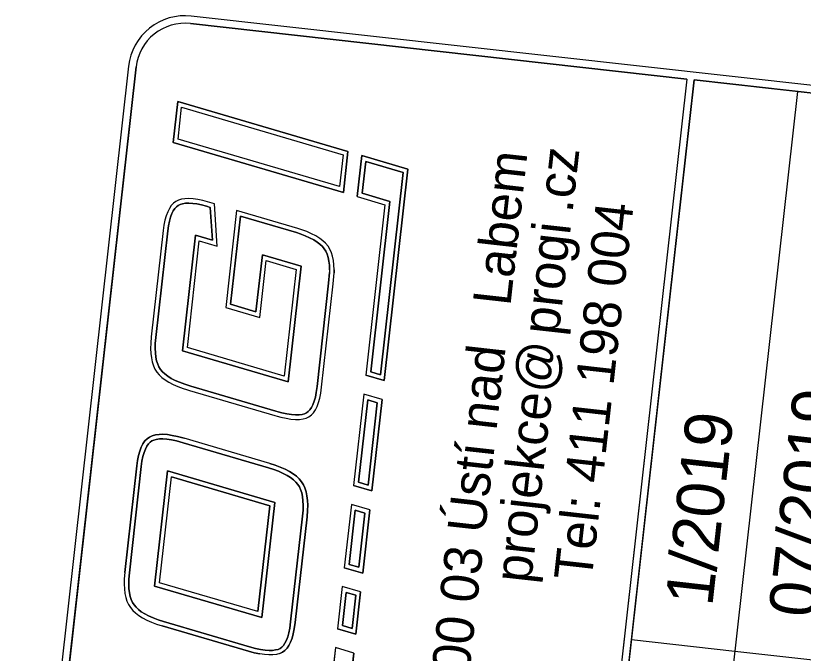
# Model space of a CAD drawing. Extents: x -734953 to -734775, y -1144697 to -1144368.
# Drawn here: x -734813.98 to -734794.21, y -1144400.21 to -1144384.19 of the extents above; entities that cross this region are included whole.
import ezdxf

# ---------------------------------------------------------------- set-up
doc = ezdxf.new("R2010")
doc.units = 0
doc.layers.add('000_rozpiska', color=7, linetype='Continuous')

# ---------------------------------------------------------------- blocks, each defined once
blk = doc.blocks.new('A$C2B726605')
at = {"layer": '000_rozpiska'}
for p, q in [((-8.894, 71.716), (-181.794, 71.716)), ((-8.894, 71.716), (-181.794, 71.716)), ((-8.894, 71.336), (-63.044, 71.336)), ((-34.759, 68.816), (-34.511, 68.836)), ((-34.511, 68.836), (-34.202, 68.844)), ((-34.202, 68.844), (-28.821, 68.844)), ((-28.821, 68.844), (-28.555, 68.837)), ((-28.555, 68.837), (-28.314, 68.816)), ((-23.536, 68.882), (-23.718, 68.8)), ((-23.336, 68.949), (-23.536, 68.882)), ((-23.113, 69), (-23.336, 68.949)), ((-22.876, 69.037), (-23.113, 69)), ((-22.611, 69.06), (-22.876, 69.037)), ((-22.599, 68.832), (-22.849, 68.811)), ((-22.293, 69.067), (-22.611, 69.06)), ((-22.29, 68.839), (-22.599, 68.832)), ((-16.9, 69.067), (-22.293, 69.067)), ((-16.903, 68.839), (-22.29, 68.839)), ((-16.644, 68.832), (-16.903, 68.839)), ((-16.631, 69.06), (-16.9, 69.067)), ((-16.41, 68.812), (-16.644, 68.832)), ((-16.382, 69.039), (-16.631, 69.06)), ((-16.158, 69.003), (-16.382, 69.039)), ((-15.946, 68.95), (-16.158, 69.003)), ((-15.774, 68.885), (-15.946, 68.95)), ((-15.623, 68.805), (-15.774, 68.885)), ((-14.003, 60.287), (-12.456, 69.067)), ((-13.731, 60.515), (-12.264, 68.839)), ((-12.456, 69.067), (-10.382, 69.067)), ((-12.264, 68.839), (-10.654, 68.839)), ((-10.654, 68.839), (-12.121, 60.515)), ((-10.382, 69.067), (-11.929, 60.287)), ((-6.424, 43.784), (-6.424, 68.866)), ((-6.044, 8.894), (-6.044, 68.866)), ((-6.044, 8.894), (-6.044, 68.866)), ((-35.877, 68.32), (-35.774, 68.43)), ((-35.774, 68.43), (-35.655, 68.523)), ((-35.655, 68.523), (-35.523, 68.603)), ((-35.523, 68.603), (-35.366, 68.674)), ((-35.366, 68.674), (-35.185, 68.734)), ((-35.185, 68.734), (-34.983, 68.781)), ((-34.983, 68.781), (-34.759, 68.816)), ((-28.314, 68.816), (-28.102, 68.782)), ((-28.102, 68.782), (-27.922, 68.735)), ((-27.922, 68.735), (-27.774, 68.68)), ((-27.774, 68.68), (-27.647, 68.612)), ((-27.647, 68.612), (-27.556, 68.541)), ((-27.556, 68.541), (-27.482, 68.458)), ((-27.482, 68.458), (-27.424, 68.363)), ((-24.14, 68.463), (-24.252, 68.312)), ((-24.014, 68.594), (-24.14, 68.463)), ((-23.875, 68.705), (-24.014, 68.594)), ((-23.718, 68.8), (-23.875, 68.705)), ((-23.744, 68.517), (-23.86, 68.425)), ((-23.612, 68.597), (-23.744, 68.517)), ((-23.453, 68.67), (-23.612, 68.597)), ((-23.274, 68.729), (-23.453, 68.67)), ((-23.07, 68.776), (-23.274, 68.729)), ((-22.849, 68.811), (-23.07, 68.776)), ((-16.203, 68.779), (-16.41, 68.812)), ((-16.014, 68.732), (-16.203, 68.779)), ((-15.868, 68.677), (-16.014, 68.732)), ((-15.744, 68.612), (-15.868, 68.677)), ((-15.646, 68.54), (-15.744, 68.612)), ((-15.57, 68.458), (-15.646, 68.54)), ((-15.494, 68.711), (-15.623, 68.805)), ((-15.513, 68.368), (-15.57, 68.458)), ((-15.389, 68.598), (-15.494, 68.711)), ((-15.31, 68.474), (-15.389, 68.598)), ((-15.247, 68.325), (-15.31, 68.474)), ((-36.072, 68.03), (-35.977, 68.188)), ((-35.977, 68.188), (-35.877, 68.32)), ((-27.424, 68.363), (-27.377, 68.245)), ((-27.377, 68.245), (-27.339, 68.093)), ((-27.339, 68.093), (-27.316, 67.921)), ((-24.358, 68.136), (-24.456, 67.934)), ((-24.252, 68.312), (-24.358, 68.136)), ((-24.062, 68.185), (-24.157, 68.028)), ((-23.966, 68.315), (-24.062, 68.185)), ((-23.86, 68.425), (-23.966, 68.315)), ((-15.462, 68.25), (-15.513, 68.368)), ((-15.425, 68.113), (-15.462, 68.25)), ((-15.401, 67.946), (-15.425, 68.113)), ((-15.201, 68.16), (-15.247, 68.325)), ((-15.174, 67.968), (-15.201, 68.16)), ((-36.313, 67.406), (-36.24, 67.64)), ((-36.24, 67.64), (-36.158, 67.849)), ((-36.158, 67.849), (-36.072, 68.03)), ((-27.309, 67.715), (-27.318, 67.49)), ((-27.316, 67.921), (-27.309, 67.715)), ((-24.542, 67.709), (-24.617, 67.47)), ((-24.456, 67.934), (-24.542, 67.709)), ((-24.247, 67.843), (-24.327, 67.634)), ((-24.157, 68.028), (-24.247, 67.843)), ((-15.39, 67.746), (-15.401, 67.946)), ((-15.396, 67.53), (-15.39, 67.746)), ((-15.161, 67.749), (-15.174, 67.968)), ((-15.168, 67.516), (-15.161, 67.749)), ((-36.377, 67.15), (-36.313, 67.406)), ((-35.686, 61.98), (-34.711, 67.51)), ((-35.414, 62.208), (-34.52, 67.282)), ((-34.711, 67.51), (-28.895, 67.51)), ((-34.52, 67.282), (-29.166, 67.282)), ((-30.06, 62.208), (-29.166, 67.282)), ((-29.869, 61.98), (-28.895, 67.51)), ((-27.318, 67.49), (-27.343, 67.228)), ((-24.617, 67.47), (-24.689, 67.189)), ((-24.398, 67.408), (-24.466, 67.138)), ((-24.327, 67.634), (-24.398, 67.408)), ((-23.773, 61.981), (-22.812, 67.436)), ((-22.812, 67.436), (-16.956, 67.436)), ((-16.956, 67.436), (-17.109, 66.562)), ((-15.455, 67.047), (-15.418, 67.292)), ((-15.418, 67.292), (-15.396, 67.53)), ((-15.23, 67.01), (-15.192, 67.265)), ((-15.192, 67.265), (-15.168, 67.516)), ((-37.443, 62.463), (-36.658, 66.917)), ((-37.218, 62.426), (-36.434, 66.871)), ((-36.434, 66.871), (-36.377, 67.15)), ((-27.394, 66.891), (-28.17, 62.485)), ((-27.946, 62.446), (-27.168, 66.857)), ((-27.343, 67.228), (-27.394, 66.891)), ((-24.755, 66.868), (-25.53, 62.465)), ((-24.723, 67.024), (-24.755, 66.868)), ((-24.689, 67.189), (-24.723, 67.024)), ((-24.499, 66.978), (-24.531, 66.825)), ((-24.466, 67.138), (-24.499, 66.978)), ((-23.501, 62.209), (-22.62, 67.208)), ((-22.62, 67.208), (-17.227, 67.208)), ((-17.227, 67.208), (-17.39, 66.281)), ((-17.109, 66.562), (-15.489, 66.851)), ((-15.489, 66.851), (-15.455, 67.047)), ((-15.293, 66.654), (-15.23, 67.01)), ((-24.531, 66.825), (-25.305, 62.43)), ((-17.39, 66.281), (-15.293, 66.654)), ((-20.41, 65.519), (-20.721, 63.755)), ((-20.219, 65.291), (-20.45, 63.983)), ((-15.492, 65.519), (-20.41, 65.519)), ((-15.764, 65.291), (-20.219, 65.291)), ((-16.272, 62.408), (-15.764, 65.291)), ((-16.049, 62.363), (-15.492, 65.519)), ((-20.721, 63.755), (-17.836, 63.755)), ((-20.45, 63.983), (-17.564, 63.983)), ((-17.836, 63.755), (-18.108, 62.209)), ((-17.564, 63.983), (-17.916, 61.981)), ((-37.288, 61.87), (-37.262, 62.134)), ((-37.262, 62.134), (-37.218, 62.426)), ((-35.414, 62.208), (-30.06, 62.208)), ((-28.229, 62.211), (-28.289, 61.967)), ((-28.168, 62.494), (-28.229, 62.211)), ((-25.574, 62.154), (-25.602, 61.884)), ((-25.547, 62.345), (-25.574, 62.154)), ((-25.53, 62.465), (-25.547, 62.345)), ((-25.348, 62.126), (-25.375, 61.868)), ((-25.321, 62.313), (-25.348, 62.126)), ((-25.305, 62.43), (-25.321, 62.313)), ((-18.108, 62.209), (-23.501, 62.209)), ((-16.383, 61.95), (-16.316, 62.214)), ((-16.316, 62.214), (-16.272, 62.408)), ((-16.163, 61.888), (-16.095, 62.161)), ((-16.095, 62.161), (-16.049, 62.363)), ((-37.298, 61.64), (-37.288, 61.87)), ((-35.686, 61.98), (-29.869, 61.98)), ((-28.367, 61.72), (-28.448, 61.51)), ((-28.289, 61.967), (-28.367, 61.72)), ((-25.602, 61.884), (-25.612, 61.64)), ((-25.375, 61.868), (-25.384, 61.64)), ((-17.916, 61.981), (-23.773, 61.981)), ((-16.537, 61.505), (-16.456, 61.717)), ((-16.456, 61.717), (-16.383, 61.95)), ((-16.241, 61.642), (-16.163, 61.888)), ((-37.291, 61.435), (-37.298, 61.64)), ((-37.268, 61.258), (-37.291, 61.435)), ((-28.537, 61.326), (-28.63, 61.17)), ((-28.448, 61.51), (-28.537, 61.326)), ((-25.612, 61.64), (-25.605, 61.413)), ((-25.605, 61.413), (-25.579, 61.21)), ((-25.384, 61.64), (-25.377, 61.431)), ((-25.377, 61.431), (-25.354, 61.252)), ((-16.719, 61.167), (-16.626, 61.321)), ((-16.626, 61.321), (-16.537, 61.505)), ((-16.426, 61.212), (-16.328, 61.415)), ((-16.328, 61.415), (-16.241, 61.642)), ((-37.231, 61.111), (-37.268, 61.258)), ((-37.184, 60.99), (-37.231, 61.111)), ((-37.126, 60.896), (-37.184, 60.99)), ((-28.835, 60.928), (-28.949, 60.838)), ((-28.729, 61.038), (-28.835, 60.928)), ((-28.63, 61.17), (-28.729, 61.038)), ((-25.579, 61.21), (-25.534, 61.032)), ((-25.534, 61.032), (-25.477, 60.887)), ((-25.354, 61.252), (-25.317, 61.102)), ((-25.317, 61.102), (-25.272, 60.989)), ((-25.272, 60.989), (-25.213, 60.893)), ((-17.039, 60.833), (-16.924, 60.924)), ((-16.924, 60.924), (-16.816, 61.036)), ((-16.816, 61.036), (-16.719, 61.167)), ((-16.642, 60.889), (-16.53, 61.04)), ((-16.53, 61.04), (-16.426, 61.212)), ((-37.055, 60.819), (-37.126, 60.896)), ((-36.959, 60.747), (-37.055, 60.819)), ((-36.839, 60.683), (-36.959, 60.747)), ((-36.687, 60.627), (-36.839, 60.683)), ((-36.506, 60.581), (-36.687, 60.627)), ((-36.295, 60.547), (-36.506, 60.581)), ((-36.059, 60.526), (-36.295, 60.547)), ((-35.746, 60.519), (-36.059, 60.526)), ((-30.401, 60.519), (-35.746, 60.519)), ((-30.095, 60.527), (-30.401, 60.519)), ((-29.849, 60.547), (-30.095, 60.527)), ((-29.624, 60.582), (-29.849, 60.547)), ((-29.421, 60.629), (-29.624, 60.582)), ((-29.242, 60.688), (-29.421, 60.629)), ((-29.082, 60.76), (-29.242, 60.688)), ((-28.949, 60.838), (-29.082, 60.76)), ((-25.477, 60.887), (-25.396, 60.755)), ((-25.396, 60.755), (-25.295, 60.643)), ((-25.295, 60.643), (-25.168, 60.55)), ((-25.213, 60.893), (-25.141, 60.813)), ((-25.168, 60.55), (-25.016, 60.469)), ((-25.141, 60.813), (-25.047, 60.744)), ((-25.047, 60.744), (-24.922, 60.677)), ((-24.922, 60.677), (-24.774, 60.621)), ((-24.774, 60.621), (-24.592, 60.576)), ((-24.592, 60.576), (-24.381, 60.543)), ((-24.381, 60.543), (-24.143, 60.522)), ((-24.143, 60.522), (-23.837, 60.515)), ((-18.622, 60.515), (-18.073, 60.532)), ((-17.938, 60.543), (-18.073, 60.532)), ((-17.938, 60.543), (-17.714, 60.577)), ((-17.714, 60.577), (-17.514, 60.623)), ((-17.514, 60.623), (-17.334, 60.683)), ((-17.334, 60.683), (-17.18, 60.751)), ((-17.252, 60.47), (-17.076, 60.547)), ((-17.18, 60.751), (-17.039, 60.833)), ((-17.076, 60.547), (-16.91, 60.645)), ((-16.91, 60.645), (-16.771, 60.755)), ((-16.771, 60.755), (-16.642, 60.889)), ((-25.016, 60.469), (-24.842, 60.403)), ((-24.842, 60.403), (-24.638, 60.353)), ((-24.638, 60.353), (-24.409, 60.316)), ((-24.409, 60.316), (-24.156, 60.295)), ((-24.156, 60.295), (-23.84, 60.287)), ((-23.84, 60.287), (-18.618, 60.287)), ((-23.837, 60.515), (-18.622, 60.515)), ((-18.618, 60.287), (-18.06, 60.305)), ((-17.912, 60.316), (-18.06, 60.305)), ((-17.912, 60.316), (-17.671, 60.353)), ((-17.671, 60.353), (-17.453, 60.403)), ((-17.453, 60.403), (-17.252, 60.47)), ((-11.929, 60.287), (-14.003, 60.287)), ((-12.121, 60.515), (-13.731, 60.515)), ((-14.128, 59.574), (-14.38, 58.143)), ((-13.937, 59.346), (-14.189, 57.915)), ((-14.128, 59.574), (-12.055, 59.574)), ((-13.937, 59.346), (-12.326, 59.346)), ((-12.326, 59.346), (-12.666, 57.421)), ((-12.055, 59.574), (-12.474, 57.193)), ((-36.779, 58.143), (-38.204, 58.143)), ((-36.946, 57.193), (-36.779, 58.143)), ((-35.996, 57.193), (-35.829, 58.143)), ((-33.691, 58.143), (-35.829, 58.143)), ((-35.724, 57.421), (-35.637, 57.915)), ((-33.963, 57.915), (-35.637, 57.915)), ((-34.05, 57.421), (-33.963, 57.915)), ((-33.859, 57.193), (-33.691, 58.143)), ((-32.909, 57.193), (-32.741, 58.143)), ((-29.535, 58.143), (-32.741, 58.143)), ((-32.637, 57.421), (-32.55, 57.915)), ((-29.807, 57.915), (-32.55, 57.915)), ((-29.894, 57.421), (-29.807, 57.915)), ((-29.702, 57.193), (-29.535, 58.143)), ((-28.752, 57.193), (-28.585, 58.143)), ((-23.954, 58.143), (-28.585, 58.143)), ((-28.481, 57.421), (-28.393, 57.915)), ((-24.225, 57.915), (-28.393, 57.915)), ((-24.312, 57.421), (-24.225, 57.915)), ((-24.121, 57.193), (-23.954, 58.143)), ((-23.171, 57.193), (-23.004, 58.143)), ((-14.38, 58.143), (-23.004, 58.143)), ((-22.899, 57.421), (-22.812, 57.915)), ((-14.189, 57.915), (-22.812, 57.915)), ((-34.05, 57.421), (-35.724, 57.421)), ((-29.894, 57.421), (-32.637, 57.421)), ((-24.312, 57.421), (-28.481, 57.421)), ((-12.666, 57.421), (-22.899, 57.421)), ((-36.946, 57.193), (-38.371, 57.193)), ((-33.859, 57.193), (-35.996, 57.193)), ((-29.702, 57.193), (-32.909, 57.193)), ((-24.121, 57.193), (-28.752, 57.193)), ((-12.474, 57.193), (-23.171, 57.193)), ((-6.424, 43.784), (-63.044, 43.784)), ((-6.424, 43.404), (-63.044, 43.404)), ((-34.734, 38.179), (-34.734, 43.404)), ((-6.424, 22.504), (-6.424, 43.404)), ((-6.424, 38.179), (-63.044, 38.179)), ((-34.734, 32.954), (-34.734, 38.179))]:
    blk.add_line(p, q, dxfattribs=at)
for points in [[(-63.044, 43.784), (-63.044, 71.336), (-8.894, 71.336)], [(-6.424, 68.866), (-6.424, 43.784), (-63.044, 43.784)], [(-28.055, 69.005), (-28.286, 69.042), (-28.542, 69.065), (-28.815, 69.072), (-34.205, 69.072), (-34.524, 69.064), (-34.786, 69.043), (-35.027, 69.005), (-35.246, 68.954), (-35.449, 68.887), (-35.629, 68.805), (-35.786, 68.711), (-35.928, 68.598), (-36.052, 68.467), (-36.166, 68.316), (-36.273, 68.138), (-36.368, 67.94), (-36.455, 67.716), (-36.532, 67.468), (-36.599, 67.2), (-36.658, 66.917), (-37.443, 62.463), (-37.489, 62.162), (-37.516, 61.886)], [(-37.388, 60.887), (-37.309, 60.758), (-37.209, 60.649), (-37.082, 60.554), (-36.933, 60.474), (-36.755, 60.409), (-36.552, 60.357), (-36.323, 60.321), (-36.071, 60.299), (-35.752, 60.291), (-30.398, 60.291), (-30.083, 60.299), (-29.822, 60.321), (-29.581, 60.358), (-29.359, 60.41), (-29.16, 60.475), (-28.977, 60.557), (-28.82, 60.65), (-28.682, 60.759), (-28.555, 60.89), (-28.441, 61.042), (-28.336, 61.217), (-28.238, 61.419), (-28.152, 61.644), (-28.07, 61.905), (-28.007, 62.16), (-27.946, 62.446), (-27.168, 66.857), (-27.117, 67.2), (-27.09, 67.475), (-27.081, 67.715), (-27.089, 67.94), (-27.115, 68.135), (-27.159, 68.315), (-27.219, 68.465), (-27.298, 68.595), (-27.4, 68.709), (-27.523, 68.804), (-27.68, 68.888), (-27.853, 68.953), (-28.055, 69.005)], [(-27.309, 67.715), (-27.316, 67.921), (-27.339, 68.093), (-27.377, 68.245), (-27.424, 68.363), (-27.482, 68.458), (-27.556, 68.541), (-27.647, 68.612), (-27.774, 68.68), (-27.922, 68.735), (-28.102, 68.782), (-28.314, 68.816), (-28.555, 68.837), (-28.821, 68.844), (-34.202, 68.844), (-34.511, 68.836), (-34.759, 68.816), (-34.983, 68.781), (-35.185, 68.734), (-35.366, 68.674), (-35.523, 68.603), (-35.655, 68.523), (-35.774, 68.43), (-35.877, 68.32), (-35.977, 68.188), (-36.072, 68.03), (-36.158, 67.849), (-36.24, 67.64), (-36.313, 67.406), (-36.377, 67.15), (-36.434, 66.871), (-37.218, 62.426), (-37.262, 62.134), (-37.288, 61.87), (-37.298, 61.64), (-37.291, 61.435), (-37.268, 61.258), (-37.231, 61.111), (-37.184, 60.99), (-37.126, 60.896), (-37.055, 60.819), (-36.959, 60.747), (-36.839, 60.683), (-36.687, 60.627), (-36.506, 60.581), (-36.295, 60.547), (-36.059, 60.526), (-35.746, 60.519), (-30.401, 60.519), (-30.095, 60.527), (-29.849, 60.547), (-29.624, 60.582), (-29.421, 60.629), (-29.242, 60.688), (-29.082, 60.76), (-28.949, 60.838), (-28.835, 60.928), (-28.729, 61.038), (-28.63, 61.17), (-28.537, 61.326), (-28.448, 61.51), (-28.367, 61.72), (-28.289, 61.967), (-28.229, 62.211), (-28.169, 62.489), (-27.394, 66.891), (-27.343, 67.228), (-27.318, 67.49), (-27.309, 67.715)], [(-28.821, 68.844), (-28.555, 68.837), (-28.314, 68.816), (-28.102, 68.782), (-27.922, 68.735), (-27.774, 68.68), (-27.647, 68.612), (-27.556, 68.541), (-27.482, 68.458), (-27.424, 68.363), (-27.377, 68.245), (-27.339, 68.093), (-27.316, 67.921), (-27.309, 67.715), (-27.318, 67.49), (-27.343, 67.228), (-27.394, 66.891), (-28.169, 62.489), (-28.229, 62.211), (-28.289, 61.967), (-28.367, 61.72), (-28.448, 61.51), (-28.537, 61.326), (-28.63, 61.17), (-28.729, 61.038), (-28.835, 60.928), (-28.949, 60.838), (-29.082, 60.76), (-29.242, 60.688), (-29.421, 60.629), (-29.624, 60.582), (-29.849, 60.547), (-30.095, 60.527), (-30.401, 60.519), (-35.746, 60.519), (-36.059, 60.526), (-36.295, 60.547), (-36.506, 60.581), (-36.687, 60.627), (-36.839, 60.683), (-36.959, 60.747), (-37.055, 60.819), (-37.126, 60.896), (-37.184, 60.99), (-37.231, 61.111), (-37.268, 61.258), (-37.291, 61.435), (-37.298, 61.64), (-37.288, 61.87), (-37.262, 62.134), (-37.218, 62.426), (-36.434, 66.871), (-36.377, 67.15), (-36.313, 67.406), (-36.24, 67.64), (-36.158, 67.849), (-36.072, 68.03), (-35.977, 68.188), (-35.877, 68.32), (-35.774, 68.43), (-35.655, 68.523), (-35.523, 68.603), (-35.366, 68.674), (-35.185, 68.734), (-34.983, 68.781), (-34.759, 68.816), (-34.511, 68.836), (-34.202, 68.844), (-28.821, 68.844)], [(-34.205, 69.072), (-34.524, 69.064), (-34.786, 69.043), (-35.027, 69.005), (-35.246, 68.954), (-35.449, 68.887), (-35.629, 68.805), (-35.786, 68.711), (-35.928, 68.598), (-36.052, 68.467), (-36.166, 68.316), (-36.273, 68.138), (-36.368, 67.94), (-36.455, 67.716), (-36.532, 67.468), (-36.599, 67.2), (-36.658, 66.917)], [(-34.205, 69.072), (-28.815, 69.072), (-28.542, 69.065), (-28.286, 69.042), (-28.055, 69.005), (-27.853, 68.953), (-27.68, 68.888), (-27.523, 68.804), (-27.4, 68.709), (-27.298, 68.595), (-27.219, 68.465), (-27.159, 68.315), (-27.115, 68.135), (-27.089, 67.94), (-27.081, 67.715), (-27.09, 67.475), (-27.117, 67.2), (-27.168, 66.857)], [(-15.946, 68.95), (-16.158, 69.003), (-16.382, 69.039), (-16.631, 69.06), (-16.9, 69.067), (-22.293, 69.067), (-22.611, 69.06), (-22.876, 69.037), (-23.113, 69), (-23.336, 68.949), (-23.536, 68.882), (-23.718, 68.8), (-23.875, 68.705), (-24.014, 68.594), (-24.14, 68.463), (-24.252, 68.312), (-24.358, 68.136), (-24.456, 67.934), (-24.542, 67.709), (-24.617, 67.47), (-24.689, 67.189), (-24.723, 67.024), (-24.755, 66.868), (-25.53, 62.465), (-25.547, 62.345), (-25.574, 62.154), (-25.602, 61.884), (-25.612, 61.64), (-25.605, 61.413), (-25.579, 61.21), (-25.534, 61.032), (-25.477, 60.887), (-25.396, 60.755), (-25.295, 60.643), (-25.168, 60.55), (-25.016, 60.469), (-24.842, 60.403), (-24.638, 60.353), (-24.409, 60.316), (-24.156, 60.295), (-23.84, 60.287), (-18.618, 60.287), (-18.06, 60.305), (-17.912, 60.316), (-17.671, 60.353), (-17.453, 60.403), (-17.252, 60.47), (-17.076, 60.547), (-16.91, 60.645), (-16.771, 60.755), (-16.642, 60.889), (-16.53, 61.04), (-16.426, 61.212), (-16.328, 61.415), (-16.241, 61.642), (-16.163, 61.888), (-16.095, 62.161), (-16.049, 62.363), (-15.492, 65.519), (-20.41, 65.519), (-20.721, 63.755), (-17.836, 63.755), (-18.108, 62.209), (-23.501, 62.209), (-22.62, 67.208), (-17.227, 67.208), (-17.39, 66.281), (-15.293, 66.654), (-15.23, 67.01), (-15.192, 67.265), (-15.168, 67.516), (-15.161, 67.749), (-15.174, 67.968), (-15.201, 68.16), (-15.247, 68.325), (-15.31, 68.474), (-15.389, 68.598), (-15.494, 68.711), (-15.623, 68.805), (-15.774, 68.885), (-15.946, 68.95)], [(-16.903, 68.839), (-16.644, 68.832), (-16.41, 68.812), (-16.203, 68.779), (-16.014, 68.732), (-15.868, 68.677), (-15.744, 68.612), (-15.646, 68.54), (-15.57, 68.458), (-15.513, 68.368), (-15.462, 68.25), (-15.425, 68.113), (-15.401, 67.946), (-15.39, 67.746), (-15.396, 67.53), (-15.418, 67.292), (-15.455, 67.047), (-15.489, 66.851), (-17.109, 66.562), (-16.956, 67.436), (-22.812, 67.436), (-23.773, 61.981), (-17.916, 61.981), (-17.564, 63.983), (-20.45, 63.983), (-20.219, 65.291), (-15.764, 65.291), (-16.272, 62.408), (-16.316, 62.214), (-16.383, 61.95), (-16.456, 61.717), (-16.537, 61.505), (-16.626, 61.321), (-16.719, 61.167), (-16.816, 61.036), (-16.924, 60.924), (-17.039, 60.833), (-17.18, 60.751), (-17.334, 60.683), (-17.514, 60.623), (-17.714, 60.577), (-17.938, 60.543), (-18.073, 60.532), (-18.622, 60.515), (-23.837, 60.515), (-24.143, 60.522), (-24.381, 60.543), (-24.592, 60.576), (-24.774, 60.621), (-24.922, 60.677), (-25.047, 60.744), (-25.141, 60.813), (-25.213, 60.893), (-25.272, 60.989), (-25.317, 61.102), (-25.354, 61.252), (-25.377, 61.431), (-25.384, 61.64), (-25.375, 61.868), (-25.348, 62.126), (-25.321, 62.313), (-25.305, 62.43), (-24.531, 66.825), (-24.499, 66.978), (-24.466, 67.138), (-24.398, 67.408), (-24.327, 67.634), (-24.247, 67.843), (-24.157, 68.028), (-24.062, 68.185), (-23.966, 68.315), (-23.86, 68.425), (-23.744, 68.517), (-23.612, 68.597), (-23.453, 68.67), (-23.274, 68.729), (-23.07, 68.776), (-22.849, 68.811), (-22.599, 68.832), (-22.29, 68.839), (-16.903, 68.839)], [(-10.382, 69.067), (-12.456, 69.067), (-14.003, 60.287), (-11.929, 60.287), (-10.382, 69.067)], [(-10.654, 68.839), (-12.121, 60.515), (-13.731, 60.515), (-12.264, 68.839), (-10.654, 68.839)], [(-28.895, 67.51), (-29.869, 61.98), (-35.686, 61.98), (-34.711, 67.51), (-28.895, 67.51)], [(-28.895, 67.51), (-34.711, 67.51), (-35.686, 61.98), (-29.869, 61.98), (-28.895, 67.51)], [(-29.166, 67.282), (-30.06, 62.208), (-35.414, 62.208), (-34.52, 67.282), (-29.166, 67.282)], [(-35.752, 60.291), (-36.071, 60.299), (-36.323, 60.321), (-36.552, 60.357), (-36.755, 60.409), (-36.933, 60.474), (-37.082, 60.554), (-37.209, 60.649), (-37.309, 60.758), (-37.388, 60.887), (-37.449, 61.041), (-37.493, 61.216), (-37.518, 61.417), (-37.526, 61.641), (-37.516, 61.886), (-37.489, 62.162), (-37.443, 62.463)], [(-27.946, 62.446), (-28.007, 62.16), (-28.07, 61.905), (-28.152, 61.644), (-28.238, 61.419), (-28.336, 61.217), (-28.441, 61.042), (-28.555, 60.89), (-28.682, 60.759), (-28.82, 60.65), (-28.977, 60.557), (-29.16, 60.475), (-29.359, 60.41), (-29.581, 60.358), (-29.822, 60.321), (-30.083, 60.299), (-30.398, 60.291), (-35.752, 60.291)], [(-12.055, 59.574), (-14.128, 59.574), (-14.38, 58.143), (-23.004, 58.143), (-23.171, 57.193), (-12.474, 57.193), (-12.055, 59.574)], [(-12.326, 59.346), (-12.666, 57.421), (-22.899, 57.421), (-22.812, 57.915), (-14.189, 57.915), (-13.937, 59.346), (-12.326, 59.346)], [(-12.326, 59.346), (-13.937, 59.346), (-14.189, 57.915), (-22.812, 57.915), (-22.899, 57.421), (-12.666, 57.421), (-12.326, 59.346)], [(-36.779, 58.143), (-38.204, 58.143), (-38.371, 57.193), (-36.946, 57.193), (-36.779, 58.143)], [(-33.691, 58.143), (-35.829, 58.143), (-35.996, 57.193), (-33.859, 57.193), (-33.691, 58.143)], [(-33.963, 57.915), (-34.05, 57.421), (-35.724, 57.421), (-35.637, 57.915), (-33.963, 57.915)], [(-33.963, 57.915), (-35.637, 57.915), (-35.724, 57.421), (-34.05, 57.421), (-33.963, 57.915)], [(-29.535, 58.143), (-32.741, 58.143), (-32.909, 57.193), (-29.702, 57.193), (-29.535, 58.143)], [(-29.807, 57.915), (-29.894, 57.421), (-32.637, 57.421), (-32.55, 57.915), (-29.807, 57.915)], [(-29.807, 57.915), (-32.55, 57.915), (-32.637, 57.421), (-29.894, 57.421), (-29.807, 57.915)], [(-23.954, 58.143), (-28.585, 58.143), (-28.752, 57.193), (-24.121, 57.193), (-23.954, 58.143)], [(-24.225, 57.915), (-24.312, 57.421), (-28.481, 57.421), (-28.393, 57.915), (-24.225, 57.915)], [(-24.225, 57.915), (-28.393, 57.915), (-28.481, 57.421), (-24.312, 57.421), (-24.225, 57.915)], [(-63.044, 22.504), (-63.044, 43.404), (-6.424, 43.404), (-6.424, 22.504), (-63.044, 22.504)]]:
    blk.add_lwpolyline(points, dxfattribs=at)
for radius, start in [(2.85, 0), (2.85, 360), (2.47, 0), (2.47, 360)]:
    blk.add_arc((-8.894, 68.866), radius, start, 90, dxfattribs=at)
for s, p in [('400 03 Ústí nad', (-38.76, 51.316)), ('Labem', (-18.775, 51.316)), ('projekce@', (-32.507, 48.739)), ('progi', (-19.971, 48.739)), ('.cz', (-13.774, 48.739)), ('Tel: 411 198 004', (-32.058, 45.729))]:
    blk.add_text(s, height=1.9, dxfattribs=at).set_placement(p)

msp = doc.modelspace()

# ---------------------------------------------------------------- block references
at = {"layer": '000_rozpiska', "xscale": 0.4999999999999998, "yscale": 0.4999999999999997, "rotation": 83.61482079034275}
msp.add_blockref('A$C2B726605', (-734775.02, -1144385.03), dxfattribs=at)

# ---------------------------------------------------------------- texts
at = {"layer": '000_rozpiska'}
for s, p in [('07/2019', (-734793.903, -1144399.348)), ('1/2019', (-734796.492, -1144399.053))]:
    msp.add_text(s, height=1.1875, rotation=83.6148, dxfattribs=at).set_placement(p)

doc.saveas('drawing.dxf')
